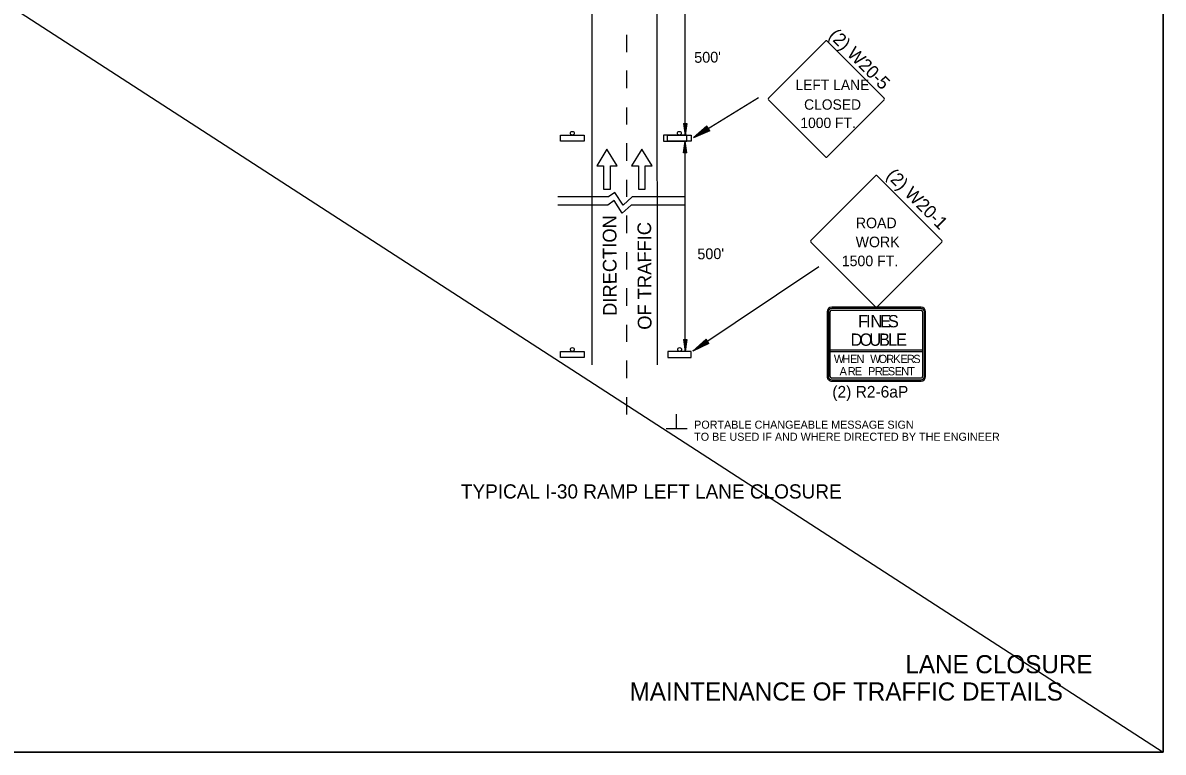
# Model space of a CAD drawing. Extents: x 1374027 to 1374537, y 380415 to 381405.
# Drawn here: x 1374452.1 to 1374537.1, y 381075.2 to 381129.5 of the extents above; entities that cross this region are included whole.
import ezdxf

# ---------------------------------------------------------------- set-up
doc = ezdxf.new("R2010")
doc.units = 0
for name, color, linetype in [('Default', 7, 'Continuous'), ('DSN_DRFT_Junk-No-Plot', 7, 'Continuous'), ('R_Border Notes', 7, 'Continuous'), ('R_Exist Surface', 7, 'Continuous')]:
    doc.layers.add(name, color=color, linetype=linetype)

msp = doc.modelspace()

# ---------------------------------------------------------------- linework, layer by layer
at = {"layer": 'Default'}
for p, q in [((1374500.818, 381099.294), (1374500.818, 381100.362)), ((1374501.596, 381099.271), (1374500.032, 381099.271))]:
    msp.add_line(p, q, dxfattribs=at)
at = {"layer": 'DSN_DRFT_Junk-No-Plot'}
msp.add_line((1374367.083, 381185.174), (1374537.083, 381075.174), dxfattribs=at)
for points in [[(1374367.083, 381185.174), (1374537.083, 381185.174), (1374537.083, 381075.174), (1374367.083, 381075.174)], [(1374367.083, 381185.174), (1374367.083, 381075.174), (1374537.083, 381075.174), (1374537.083, 381185.174)]]:
    msp.add_lwpolyline(points, close=True, dxfattribs=at)
at = {"layer": 'R_Exist Surface'}
for p, q in [((1374494.462, 381173.129), (1374494.502, 381104.039)), ((1374499.32, 381173.129), (1374499.361, 381104.042)), ((1374501.449, 381121.154), (1374501.449, 381133.684)), ((1374507.665, 381123.898), (1374511.922, 381128.156)), ((1374512.032, 381128.156), (1374516.289, 381123.898)), ((1374506.923, 381123.935), (1374502.064, 381120.965)), ((1374511.922, 381119.531), (1374507.665, 381123.789)), ((1374516.289, 381123.789), (1374512.032, 381119.531)), ((1374501.318, 381122.028), (1374501.449, 381121.154)), ((1374501.318, 381122.028), (1374501.58, 381122.028)), ((1374501.34, 381122.028), (1374501.449, 381121.3)), ((1374501.362, 381122.028), (1374501.449, 381121.45)), ((1374501.384, 381122.028), (1374501.449, 381121.596)), ((1374501.407, 381122.028), (1374501.449, 381121.744)), ((1374501.429, 381122.028), (1374501.449, 381121.89)), ((1374501.58, 381122.028), (1374501.449, 381121.154)), ((1374501.492, 381122.028), (1374501.449, 381121.744)), ((1374501.536, 381122.028), (1374501.449, 381121.45)), ((1374501.558, 381122.028), (1374501.449, 381121.3)), ((1374501.514, 381122.028), (1374501.449, 381121.596)), ((1374501.47, 381122.028), (1374501.449, 381121.89)), ((1374503.08, 381121.817), (1374502.064, 381120.965)), ((1374503.285, 381121.481), (1374502.064, 381120.965)), ((1374503.097, 381121.789), (1374502.251, 381121.079)), ((1374503.268, 381121.509), (1374502.251, 381121.079)), ((1374503.115, 381121.76), (1374502.443, 381121.197)), ((1374503.251, 381121.538), (1374502.443, 381121.197)), ((1374503.132, 381121.732), (1374502.63, 381121.311)), ((1374503.234, 381121.566), (1374502.63, 381121.311)), ((1374503.149, 381121.704), (1374502.819, 381121.427)), ((1374503.216, 381121.595), (1374502.819, 381121.427)), ((1374503.167, 381121.675), (1374503.006, 381121.541)), ((1374503.199, 381121.623), (1374503.006, 381121.541)), ((1374503.285, 381121.481), (1374503.08, 381121.817)), ((1374501.318, 381119.831), (1374501.449, 381120.706)), ((1374501.34, 381119.831), (1374501.449, 381120.56)), ((1374501.449, 381105.043), (1374501.449, 381120.706)), ((1374501.58, 381119.831), (1374501.449, 381120.706)), ((1374501.558, 381119.831), (1374501.449, 381120.56)), ((1374501.58, 381119.831), (1374501.318, 381119.831)), ((1374501.362, 381119.831), (1374501.449, 381120.409)), ((1374501.384, 381119.831), (1374501.449, 381120.264)), ((1374501.406, 381119.831), (1374501.449, 381120.115)), ((1374501.429, 381119.831), (1374501.449, 381119.969)), ((1374501.536, 381119.831), (1374501.449, 381120.409)), ((1374501.514, 381119.831), (1374501.449, 381120.264)), ((1374501.491, 381119.831), (1374501.449, 381120.115)), ((1374501.47, 381119.831), (1374501.449, 381119.969)), ((1374510.823, 381113.303), (1374515.643, 381118.123)), ((1374515.767, 381118.123), (1374520.587, 381113.303)), ((1374515.643, 381108.359), (1374510.823, 381113.179)), ((1374520.587, 381113.179), (1374515.767, 381108.359)), ((1374511.408, 381111.336), (1374502.03, 381105.053)), ((1374512.033, 381107.989), (1374512.033, 381103.17)), ((1374512.129, 381107.989), (1374512.129, 381103.17)), ((1374512.262, 381103.17), (1374512.262, 381107.989)), ((1374519.033, 381108.333), (1374512.377, 381108.333)), ((1374519.033, 381108.238), (1374512.377, 381108.238)), ((1374512.377, 381108.104), (1374519.033, 381108.104)), ((1374519.147, 381107.989), (1374519.147, 381103.17)), ((1374519.281, 381103.17), (1374519.281, 381107.989)), ((1374519.377, 381103.17), (1374519.377, 381107.989)), ((1374501.318, 381105.917), (1374501.449, 381105.043)), ((1374501.318, 381105.917), (1374501.58, 381105.917)), ((1374501.34, 381105.917), (1374501.449, 381105.189)), ((1374501.362, 381105.917), (1374501.449, 381105.339)), ((1374501.384, 381105.917), (1374501.449, 381105.485)), ((1374501.407, 381105.917), (1374501.449, 381105.633)), ((1374501.429, 381105.917), (1374501.449, 381105.779)), ((1374501.58, 381105.917), (1374501.449, 381105.043)), ((1374501.492, 381105.917), (1374501.449, 381105.633)), ((1374501.536, 381105.917), (1374501.449, 381105.339)), ((1374501.558, 381105.917), (1374501.449, 381105.189)), ((1374501.514, 381105.917), (1374501.449, 381105.485)), ((1374501.47, 381105.917), (1374501.449, 381105.779)), ((1374503.01, 381105.947), (1374502.03, 381105.054)), ((1374503.229, 381105.62), (1374502.03, 381105.054)), ((1374503.029, 381105.92), (1374502.212, 381105.175)), ((1374503.211, 381105.647), (1374502.212, 381105.175)), ((1374503.047, 381105.892), (1374502.4, 381105.301)), ((1374503.192, 381105.675), (1374502.4, 381105.301)), ((1374503.065, 381105.865), (1374502.581, 381105.423)), ((1374503.174, 381105.702), (1374502.581, 381105.423)), ((1374503.084, 381105.837), (1374502.766, 381105.546)), ((1374503.155, 381105.731), (1374502.766, 381105.546)), ((1374503.103, 381105.809), (1374502.948, 381105.668)), ((1374503.137, 381105.758), (1374502.948, 381105.668)), ((1374503.229, 381105.62), (1374503.01, 381105.947)), ((1374512.262, 381105.015), (1374512.262, 381105.149)), ((1374512.262, 381105.149), (1374519.147, 381105.149)), ((1374519.147, 381105.015), (1374512.262, 381105.015)), ((1374519.147, 381105.149), (1374519.147, 381105.015)), ((1374519.033, 381103.055), (1374512.377, 381103.055)), ((1374512.377, 381102.921), (1374519.033, 381102.921)), ((1374512.377, 381102.825), (1374519.033, 381102.825))]:
    msp.add_line(p, q, dxfattribs=at)
for points in [[(1374497.075, 381128.626), (1374497.076, 381127.343)], [(1374497.076, 381125.96), (1374497.077, 381124.644)], [(1374497.078, 381123.226), (1374497.079, 381121.944)], [(1374497.08, 381120.561), (1374497.08, 381119.245)], [(1374497.081, 381117.827), (1374497.082, 381116.545)], [(1374501.483, 381116.548), (1374497.501, 381116.548), (1374496.827, 381115.941), (1374496.219, 381116.886), (1374495.747, 381116.548), (1374491.967, 381116.548)], [(1374501.483, 381115.941), (1374497.434, 381115.941), (1374496.759, 381115.333), (1374496.152, 381116.278), (1374495.679, 381115.941), (1374491.967, 381115.941)], [(1374497.083, 381115.161), (1374497.083, 381113.846)], [(1374497.084, 381112.428), (1374497.085, 381111.146)], [(1374497.085, 381109.762), (1374497.086, 381108.446)], [(1374497.087, 381107.029), (1374497.088, 381105.746)], [(1374497.088, 381104.363), (1374497.089, 381103.047)], [(1374497.09, 381101.63), (1374497.091, 381100.347)]]:
    msp.add_lwpolyline(points, dxfattribs=at)
for points in [[(1374492.17, 381121.154), (1374493.919, 381121.154), (1374493.919, 381120.706), (1374492.17, 381120.706)], [(1374501.587, 381121.154), (1374499.847, 381121.154), (1374499.847, 381120.706), (1374501.587, 381120.706)], [(1374500.146, 381121.154), (1374501.894, 381121.154), (1374501.894, 381120.706), (1374500.146, 381120.706)], [(1374495.626, 381120.117), (1374494.861, 381118.871), (1374495.371, 381118.871), (1374495.371, 381117.122), (1374495.881, 381117.122), (1374495.881, 381118.871), (1374496.391, 381118.871)], [(1374498.228, 381120.117), (1374497.463, 381118.871), (1374497.973, 381118.871), (1374497.973, 381117.122), (1374498.483, 381117.122), (1374498.483, 381118.871), (1374498.993, 381118.871)], [(1374492.17, 381105.043), (1374493.919, 381105.043), (1374493.919, 381104.595), (1374492.17, 381104.595)], [(1374501.894, 381105.043), (1374500.155, 381105.043), (1374500.155, 381104.595), (1374501.894, 381104.595)]]:
    msp.add_lwpolyline(points, close=True, dxfattribs=at)
for centre, radius, start, end in [((1374512.377, 381107.989), 0.344, 90, 180), ((1374512.377, 381107.989), 0.249, 90, 180.00001), ((1374512.377, 381107.989), 0.115, 90, 180.00001), ((1374519.033, 381107.989), 0.344, 0, 90), ((1374519.033, 381107.989), 0.249, 0, 90), ((1374519.033, 381107.989), 0.115, 0, 90), ((1374512.377, 381103.17), 0.344, 180, 270.00001), ((1374512.377, 381103.17), 0.249, 180.00001, 270), ((1374512.377, 381103.17), 0.115, 180.00001, 270), ((1374519.033, 381103.17), 0.344, 270.00001, 0.00001), ((1374519.033, 381103.17), 0.249, 270, 0.00001), ((1374519.033, 381103.17), 0.115, 270, 0.00001)]:
    msp.add_arc(centre, radius, start, end, dxfattribs=at)
for centre, major_axis, start_param, end_param in [((1374511.977, 381128.102), (0, -0.0772), 2.356194, 3.926991), ((1374507.719, 381123.844), (0, -0.0772), 3.926991, 5.497786), ((1374516.234, 381123.844), (0, 0.0772), 3.926992, 5.497787), ((1374511.977, 381119.586), (0, -0.0772), 5.497786, 7.068585), ((1374515.705, 381118.061), (0, -0.0874), 2.356194, 3.926991), ((1374510.885, 381113.241), (0, -0.0874), 3.926991, 5.497786), ((1374520.525, 381113.241), (0, 0.0874), 3.926992, 5.497787), ((1374515.705, 381108.421), (0, -0.0874), 5.497786, 7.068585)]:
    msp.add_ellipse(centre, major_axis=major_axis, ratio=0.999914, start_param=start_param, end_param=end_param, dxfattribs=at)
for centre in [(1374493.043, 381121.295), (1374501.018, 381121.295), (1374493.043, 381105.184), (1374501.041, 381105.184)]:
    msp.add_ellipse(centre, major_axis=(0, 0.141), ratio=0.999914, dxfattribs=at)

# ---------------------------------------------------------------- texts
at = {"layer": 'Default'}
for s, height, p in [('PORTABLE CHANGEABLE MESSAGE SIGN', 0.59997, (1374502.124, 381099.279)), ('TO BE USED IF AND WHERE DIRECTED BY THE ENGINEER', 0.59997, (1374502.124, 381098.38)), ('TYPICAL I-30 RAMP LEFT LANE CLOSURE', 1.05792, (1374484.737, 381094.076))]:
    msp.add_text(s, height=height, dxfattribs=at).set_placement(p)
at = {"layer": 'R_Border Notes'}
for s, p in [('LANE CLOSURE', (1374517.871, 381081.056)), ('MAINTENANCE OF TRAFFIC DETAILS', (1374497.313, 381079.024))]:
    msp.add_text(s, height=1.35, dxfattribs=at).set_placement(p)
at = {"layer": 'R_Exist Surface'}
for s, height, rotation, p in [('(2) W20-5', 0.9617, 314.99755, (1374512.091, 381128.51)), ("500'", 0.8015, 1.00009, (1374502.136, 381126.54)), ('(2) W20-1', 0.9617, 314.99755, (1374516.387, 381118.089)), ('DIRECTION', 1.02, 90.19694, (1374496.351, 381107.689)), ('OF TRAFFIC', 1.02, 90.19694, (1374498.944, 381106.653)), ("500'", 0.8015, 1.00009, (1374502.368, 381111.895))]:
    msp.add_text(s, height=height, rotation=rotation, dxfattribs=at).set_placement(p)
for s, height, p in [('LEFT LANE', 0.772, (1374509.673, 381124.515)), ('CLOSED', 0.772, (1374510.317, 381123.048)), ('1000 FT.', 0.772, (1374510.039, 381121.684)), ('ROAD', 0.7866, (1374514.176, 381114.219)), ('WORK', 0.7866, (1374514.161, 381112.804)), ('1500 FT.', 0.7866, (1374513.127, 381111.389)), ('F', 0.918, (1374514.337, 381106.832)), ('I', 0.918, (1374514.934, 381106.832)), ('N', 0.918, (1374515.264, 381106.832)), ('E', 0.918, (1374515.98, 381106.832)), ('S', 0.918, (1374516.559, 381106.832)), ('D', 0.918, (1374513.777, 381105.455)), ('O', 0.918, (1374514.456, 381105.455)), ('U', 0.918, (1374515.182, 381105.455)), ('B', 0.918, (1374515.898, 381105.455)), ('L', 0.918, (1374516.568, 381105.455)), ('E', 0.918, (1374517.164, 381105.455)), ('W', 0.612, (1374512.538, 381104.174)), ('H', 0.612, (1374513.174, 381104.174)), ('E', 0.612, (1374513.737, 381104.174)), ('N', 0.612, (1374514.221, 381104.174)), ('W', 0.612, (1374515.249, 381104.174)), ('O', 0.612, (1374515.873, 381104.174)), ('R', 0.612, (1374516.442, 381104.174)), ('K', 0.612, (1374516.962, 381104.174)), ('E', 0.612, (1374517.495, 381104.174)), ('R', 0.612, (1374517.978, 381104.174)), ('S', 0.612, (1374518.456, 381104.174)), ('A', 0.612, (1374512.963, 381103.256)), ('R', 0.612, (1374513.575, 381103.256)), ('E', 0.612, (1374514.095, 381103.256)), ('P', 0.612, (1374515.087, 381103.256)), ('R', 0.612, (1374515.595, 381103.256)), ('E', 0.612, (1374516.115, 381103.256)), ('S', 0.612, (1374516.556, 381103.256)), ('E', 0.612, (1374517.076, 381103.256)), ('N', 0.612, (1374517.559, 381103.256)), ('T', 0.612, (1374518.067, 381103.256)), ('(2) R2-6aP', 0.8655, (1374512.423, 381101.6))]:
    msp.add_text(s, height=height, dxfattribs=at).set_placement(p)

doc.saveas('drawing.dxf')
